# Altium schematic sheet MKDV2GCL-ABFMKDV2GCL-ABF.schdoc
size 127 x 101 mm
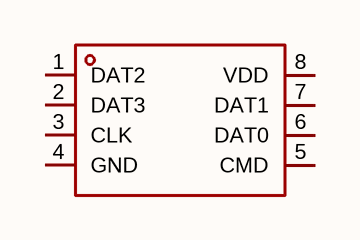
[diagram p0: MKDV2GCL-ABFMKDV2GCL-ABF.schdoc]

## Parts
U?  mkdv2gcl-abf  [LGA-8_L8.0-W6.0-P1.27-TL_MKDV1GCL-ABB]  (value not drawn)

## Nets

Not connected (* = marked no-connect by the designer): U? 1(DAT2) 2(DAT3) 3(CLK) 4(GND) 5(CMD) 6(DAT0) 7(DAT1) 8(VDD)

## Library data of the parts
U? = mkdv2gcl-abf: 存储容量:2Gbit;时钟频率(fc):50MHz;工作电压:2.7V~3.6V;; Manufacturer: MK(米客方德); AddInBom: yes; Memory Size: 2Gbit; Interface: SD接口; Clock Frequency: 50MHz; Data Retention - TDR (Year): 10年; Standby Supply Current: 80uA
